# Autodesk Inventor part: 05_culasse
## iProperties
Created: 2002-11
Part Number: 05_culasse
Material: Z-A 4G
Document SubType Name: Modélisation
Designer: poste-2
Control State: 0
Master: False
Checked Out: False
Shininess: 20.0
Length Units: 11269
Angle Units: 11279
Time Units: 11290
Mass Units: 11283
Length Display Precision: 3
Angle Display Precision: 2
Compacted: True
Density: 7.8500000000000005
Volumn: 3.2257814935651448
Area: 30.84428910282234
PropertySet Name: Model Information
Author: poste-2
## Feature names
1. Révolution1 [Revolution]
2. Extrusion1
3. Extrusion2
4. Réseau circulaire1 [Circular Pattern]
5. Perçage1 [Hole]
6. Extrusion3
7. Extrusion4
8. Extrusion5
9. Perçage2 [Hole]
10. Révolution2 [Revolution]
